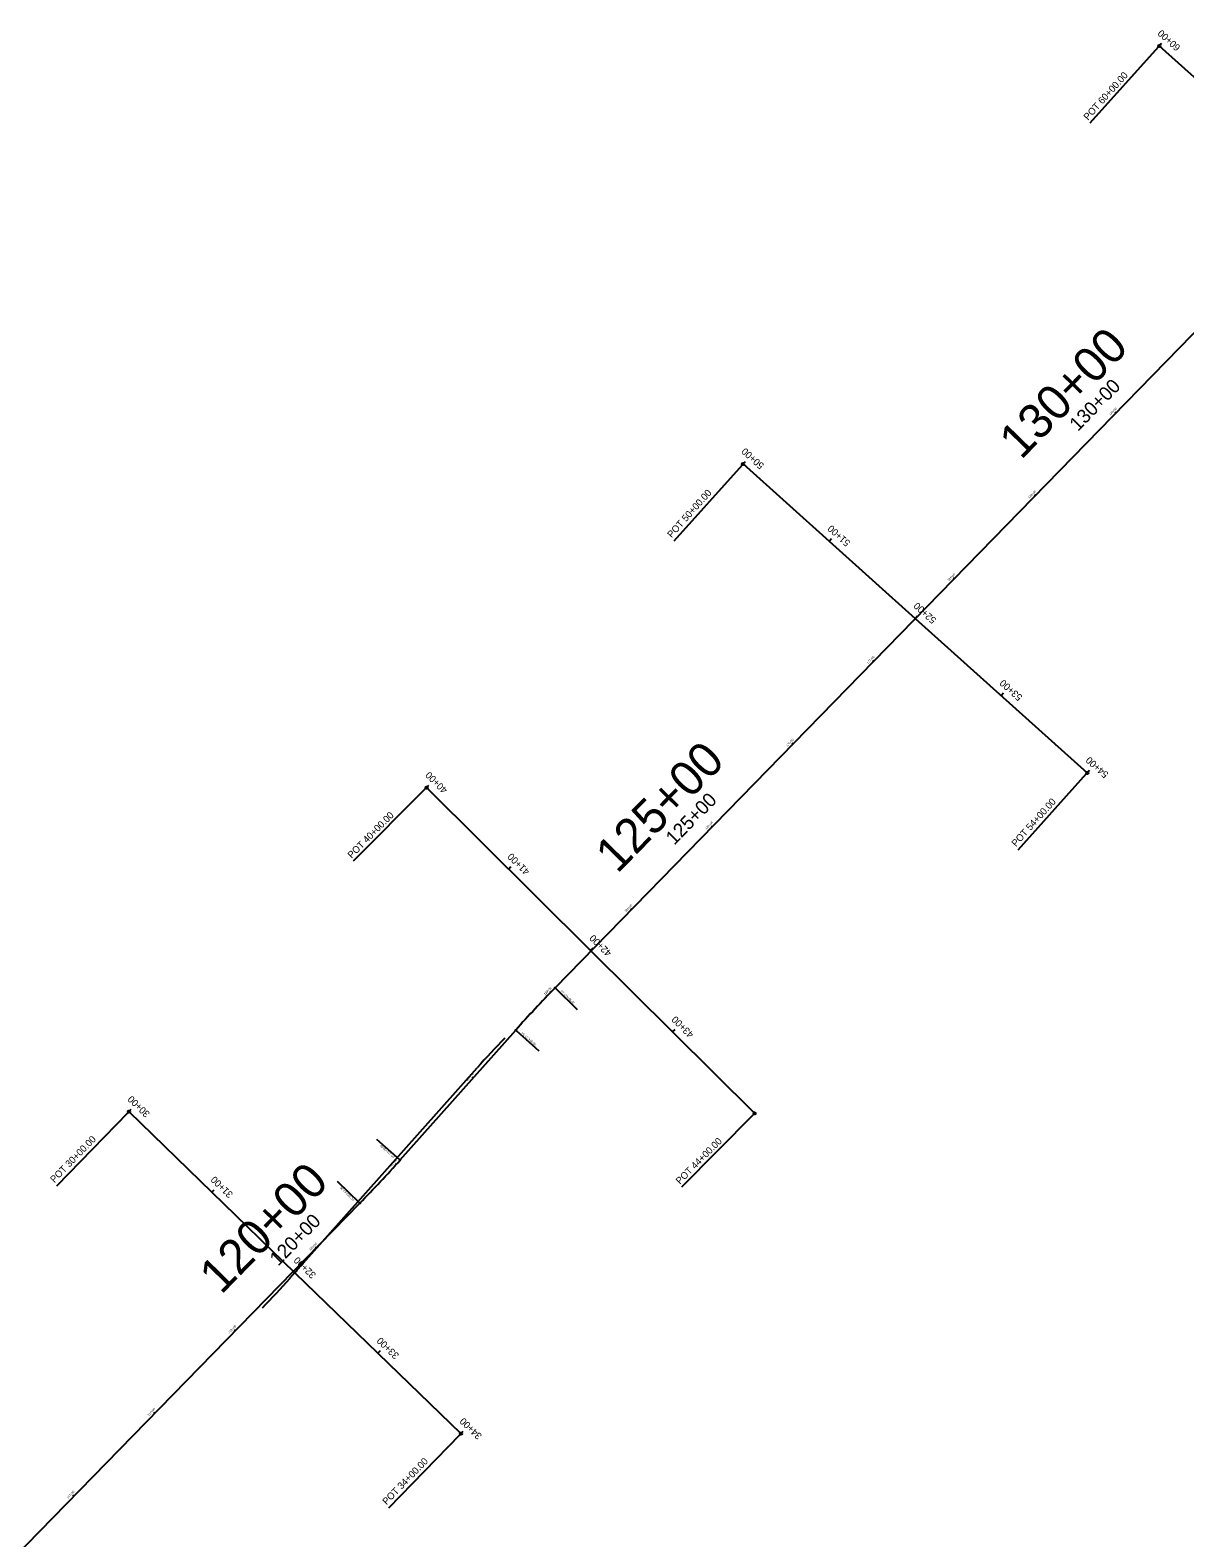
# Model space of a CAD drawing. Extents: x 2252491 to 2257126, y 13788370 to 13792743.
# Drawn here: x 2253815 to 2254813, y 13789656 to 13790960 of the extents above; entities that cross this region are included whole.
import ezdxf

# ---------------------------------------------------------------- set-up
doc = ezdxf.new("R2010")
doc.units = 0
for name, color, linetype in [('D_ALIGN_1', 7, 'Continuous'), ('D_ALIGN_ANNO_1', 7, 'Continuous'), ('D_ALIGN_ANNO_200_drn', 7, 'Continuous'), ('D_ALIGN_ANNO_BENELLI', 7, 'Continuous'), ('D_ALIGN_ANNO_DRN_300', 7, 'Continuous'), ('D_ALIGN_ANNO_QUAIL_RIDGE', 7, 'Continuous'), ('D_ALIGN_ANNO_RR_STOEGER', 7, 'Continuous'), ('D_ALIGN_ANNO_WISE_OWL', 7, 'Continuous'), ('D_ALIGN_BENELLI', 7, 'Continuous'), ('D_ALIGN_QUAIL_RIDGE', 7, 'Continuous'), ('D_ALIGN_RR_STOEGER', 7, 'Continuous'), ('D_ALIGN_WISE_OWL', 7, 'Continuous'), ('Default', 7, 'Continuous')]:
    doc.layers.add(name, color=color, linetype=linetype)

msp = doc.modelspace()

# ---------------------------------------------------------------- linework, layer by layer
at = {"layer": 'D_ALIGN_1'}
for p, q in [((2254268.7, 13790131.5), (2255037.3, 13790919.6)), ((2254134.6, 13789982.6), (2254234.7, 13790094.9)), ((2253097.1, 13788919.2), (2254099.8, 13789945.2))]:
    msp.add_line(p, q, dxfattribs=at)
for centre, start, end in [((2255056.2, 13789363.5), 135.7179, 138.3209), ((2253313.1, 13790714), 315.6588, 318.3209)]:
    msp.add_arc(centre, 1100, start, end, dxfattribs=at)
at = {"layer": 'D_ALIGN_ANNO_1'}
for p, q in [((2254753.6, 13790628.7), (2254753, 13790629.3)), ((2254683.8, 13790557.1), (2254683.2, 13790557.7)), ((2254614, 13790485.5), (2254613.3, 13790486.1)), ((2254544.2, 13790413.9), (2254543.5, 13790414.6)), ((2254474.4, 13790342.3), (2254473.7, 13790343)), ((2254404.5, 13790270.7), (2254403.9, 13790271.4)), ((2254334.7, 13790199.1), (2254334.1, 13790199.8)), ((2254264.9, 13790127.5), (2254264.3, 13790128.2)), ((2254268.9, 13790131.3), (2254287.9, 13790112.8)), ((2254234.9, 13790094.7), (2254254.7, 13790077.1)), ((2254197.7, 13790053.5), (2254197.1, 13790054.1)), ((2254134.4, 13789982.8), (2254114.6, 13790000.4)), ((2254131.2, 13789978.8), (2254130.6, 13789979.4)), ((2254099.6, 13789945.4), (2254080.6, 13789963.9)), ((2254062, 13789906.6), (2254061.4, 13789907.2)), ((2253992.2, 13789835.1), (2253991.5, 13789835.7)), ((2253922.3, 13789763.6), (2253921.6, 13789764.2)), ((2253852.4, 13789692), (2253851.7, 13789692.7))]:
    msp.add_line(p, q, dxfattribs=at)
for centre in [(2254268.7, 13790131.5), (2254234.7, 13790094.9), (2254134.6, 13789982.6), (2254099.8, 13789945.2)]:
    msp.add_circle(centre, 0.3, dxfattribs=at)
at = {"layer": 'D_ALIGN_ANNO_BENELLI'}
for p, q in [((2254094.4, 13790241.2), (2254156.7, 13790304)), ((2254157.5, 13790304.7), (2254159.6, 13790306.8)), ((2254228.4, 13790234.2), (2254230.5, 13790236.3)), ((2254299.4, 13790163.7), (2254301.5, 13790165.9)), ((2254370.3, 13790093.3), (2254372.4, 13790095.4)), ((2254378.3, 13789959.4), (2254440.6, 13790022.1))]:
    msp.add_line(p, q, dxfattribs=at)
for centre in [(2254157.5, 13790304.7), (2254441.3, 13790022.8)]:
    msp.add_circle(centre, 1, dxfattribs=at)
at = {"layer": 'D_ALIGN_ANNO_QUAIL_RIDGE'}
for p, q in [((2254371.5, 13790518), (2254430.6, 13790583.8)), ((2254431.2, 13790584.6), (2254433.2, 13790586.8)), ((2254505.7, 13790517.8), (2254507.7, 13790520)), ((2254580.1, 13790451), (2254582.1, 13790453.2)), ((2254654.5, 13790384.2), (2254656.5, 13790386.5)), ((2254669.2, 13790250.9), (2254728.3, 13790316.7)), ((2254728.9, 13790317.4), (2254730.9, 13790319.7))]:
    msp.add_line(p, q, dxfattribs=at)
for centre in [(2254431.2, 13790584.6), (2254728.9, 13790317.4)]:
    msp.add_circle(centre, 1, dxfattribs=at)
at = {"layer": 'D_ALIGN_ANNO_RR_STOEGER'}
for p, q in [((2254791.1, 13790946.1), (2254793.1, 13790948.4)), ((2254731.5, 13790879.5), (2254790.5, 13790945.4))]:
    msp.add_line(p, q, dxfattribs=at)
msp.add_circle((2254791.1, 13790946.1), 1, dxfattribs=at)
at = {"layer": 'D_ALIGN_ANNO_WISE_OWL'}
for p, q in [((2253837.9, 13789960.2), (2253899.4, 13790023.7)), ((2253900.1, 13790024.4), (2253902.2, 13790026.5)), ((2253971.9, 13789954.8), (2253974, 13789956.9)), ((2254043.7, 13789885.1), (2254045.8, 13789887.3)), ((2254115.5, 13789815.5), (2254117.6, 13789817.7)), ((2254187.3, 13789745.9), (2254189.3, 13789748)), ((2254125, 13789681.7), (2254186.6, 13789745.2))]:
    msp.add_line(p, q, dxfattribs=at)
for centre in [(2253900.1, 13790024.4), (2254187.3, 13789745.9)]:
    msp.add_circle(centre, 1, dxfattribs=at)
at = {"layer": 'D_ALIGN_BENELLI'}
for p, q in [((2254157.5, 13790304.7), (2254299.4, 13790163.7)), ((2254299.4, 13790163.7), (2254441.3, 13790022.8))]:
    msp.add_line(p, q, dxfattribs=at)
at = {"layer": 'D_ALIGN_QUAIL_RIDGE'}
for p, q in [((2254431.2, 13790584.6), (2254580.1, 13790451)), ((2254580.1, 13790451), (2254728.9, 13790317.4))]:
    msp.add_line(p, q, dxfattribs=at)
at = {"layer": 'D_ALIGN_RR_STOEGER'}
msp.add_line((2254791.1, 13790946.1), (2254929.5, 13790822.2), dxfattribs=at)
at = {"layer": 'D_ALIGN_WISE_OWL'}
for p, q in [((2253900.1, 13790024.4), (2254043.7, 13789885.1)), ((2254043.7, 13789885.1), (2254187.3, 13789745.9))]:
    msp.add_line(p, q, dxfattribs=at)
at = {"layer": 'Default'}
msp.add_line((2254039.4, 13789880.3), (2254201.4, 13790062.3), dxfattribs=at)
for centre, start, end in [((2254761.6, 13789563.7), 135.6588, 138.3333), ((2253479.2, 13790378.9), 315.6588, 318.3333)]:
    msp.add_arc(centre, 750, start, end, dxfattribs=at)

# ---------------------------------------------------------------- texts
at = {"layer": 'D_ALIGN_ANNO_1'}
for s, rotation, p in [('130+00', 45.7179, (2254748.7, 13790626.2)), ('129+00', 45.7179, (2254678.9, 13790554.6)), ('128+00', 45.7179, (2254609.1, 13790483)), ('127+00', 45.7179, (2254539.2, 13790411.5)), ('126+00', 45.7179, (2254469.4, 13790339.9)), ('125+00', 45.7179, (2254399.6, 13790268.3)), ('124+00', 45.7179, (2254329.8, 13790196.7)), ('123+00', 46.0029, (2254260, 13790125.1)), ('PT 123+05.47', 315.7179, (2254273.2, 13790128.3)), ('PC 122+55.50', 318.3209, (2254239.3, 13790092)), ('122+00', 48.3209, (2254192.9, 13790050.8)), ('PT 121+05.09', 138.3209, (2254130, 13789985.5)), ('121+00', 48.056, (2254126.4, 13789976.1)), ('PC 120+53.98', 135.6588, (2254095.3, 13789948.3)), ('120+00', 45.6588, (2254057.1, 13789904.1)), ('119+00', 45.6588, (2253987.2, 13789832.6)), ('118+00', 45.6588, (2253917.3, 13789761.1)), ('117+00', 45.6588, (2253847.4, 13789689.6))]:
    msp.add_text(s, height=1.8, rotation=rotation, dxfattribs=at).set_placement(p)
at = {"layer": 'D_ALIGN_ANNO_200_drn'}
for s, rotation, p in [('130+00', 45.7179, (2254720.8, 13790612.2)), ('125+00', 45.7179, (2254371.7, 13790254.3)), ('120+00', 45.6588, (2254029.2, 13789890.2))]:
    msp.add_text(s, height=12, rotation=rotation, dxfattribs=at).set_placement(p)
at = {"layer": 'D_ALIGN_ANNO_BENELLI'}
for s, rotation, p in [('40+00', 135.1964, (2254176.1, 13790303.1)), ('POT 40+00.00', 45.1964, (2254092.8, 13790243)), ('41+00', 135.1964, (2254247.1, 13790232.6)), ('42+00', 135.1964, (2254318, 13790162.1)), ('43+00', 135.1964, (2254389, 13790091.7)), ('POT 44+00.00', 45.1964, (2254376.6, 13789961.1))]:
    msp.add_text(s, height=6, rotation=rotation, dxfattribs=at).set_placement(p)
at = {"layer": 'D_ALIGN_ANNO_DRN_300'}
for s, rotation, p in [('130+00', 45.7179, (2254671.6, 13790587.5)), ('125+00', 45.7179, (2254322.5, 13790229.6)), ('120+00', 45.6588, (2253979.9, 13789865.5))]:
    msp.add_text(s, height=30, rotation=rotation, dxfattribs=at).set_placement(p)
at = {"layer": 'D_ALIGN_ANNO_QUAIL_RIDGE'}
for s, rotation, p in [('50+00', 138.1006, (2254449.9, 13790583.9)), ('POT 50+00.00', 48.1006, (2254369.5, 13790520.2)), ('51+00', 138.1006, (2254524.4, 13790517.1)), ('52+00', 138.1006, (2254598.8, 13790450.3)), ('53+00', 138.1006, (2254673.2, 13790383.5)), ('54+00', 138.1006, (2254747.7, 13790316.8)), ('POT 54+00.00', 48.1006, (2254667.2, 13790253.1))]:
    msp.add_text(s, height=6, rotation=rotation, dxfattribs=at).set_placement(p)
at = {"layer": 'D_ALIGN_ANNO_RR_STOEGER'}
for s, rotation, p in [('60+00', 138.135, (2254809.9, 13790945.5)), ('POT 60+00.00', 48.135, (2254729.5, 13790881.3))]:
    msp.add_text(s, height=6, rotation=rotation, dxfattribs=at).set_placement(p)
at = {"layer": 'D_ALIGN_ANNO_WISE_OWL'}
for s, rotation, p in [('30+00', 135.8716, (2253918.8, 13790023)), ('POT 30+00.00', 45.8716, (2253835.7, 13789962.4)), ('31+00', 135.8716, (2253990.6, 13789953.4)), ('32+00', 135.8716, (2254062.4, 13789883.7)), ('33+00', 135.8716, (2254134.2, 13789814.1)), ('34+00', 135.8716, (2254205.9, 13789744.5)), ('POT 34+00.00', 45.8716, (2254122.9, 13789683.9))]:
    msp.add_text(s, height=6, rotation=rotation, dxfattribs=at).set_placement(p)

doc.saveas('drawing.dxf')
